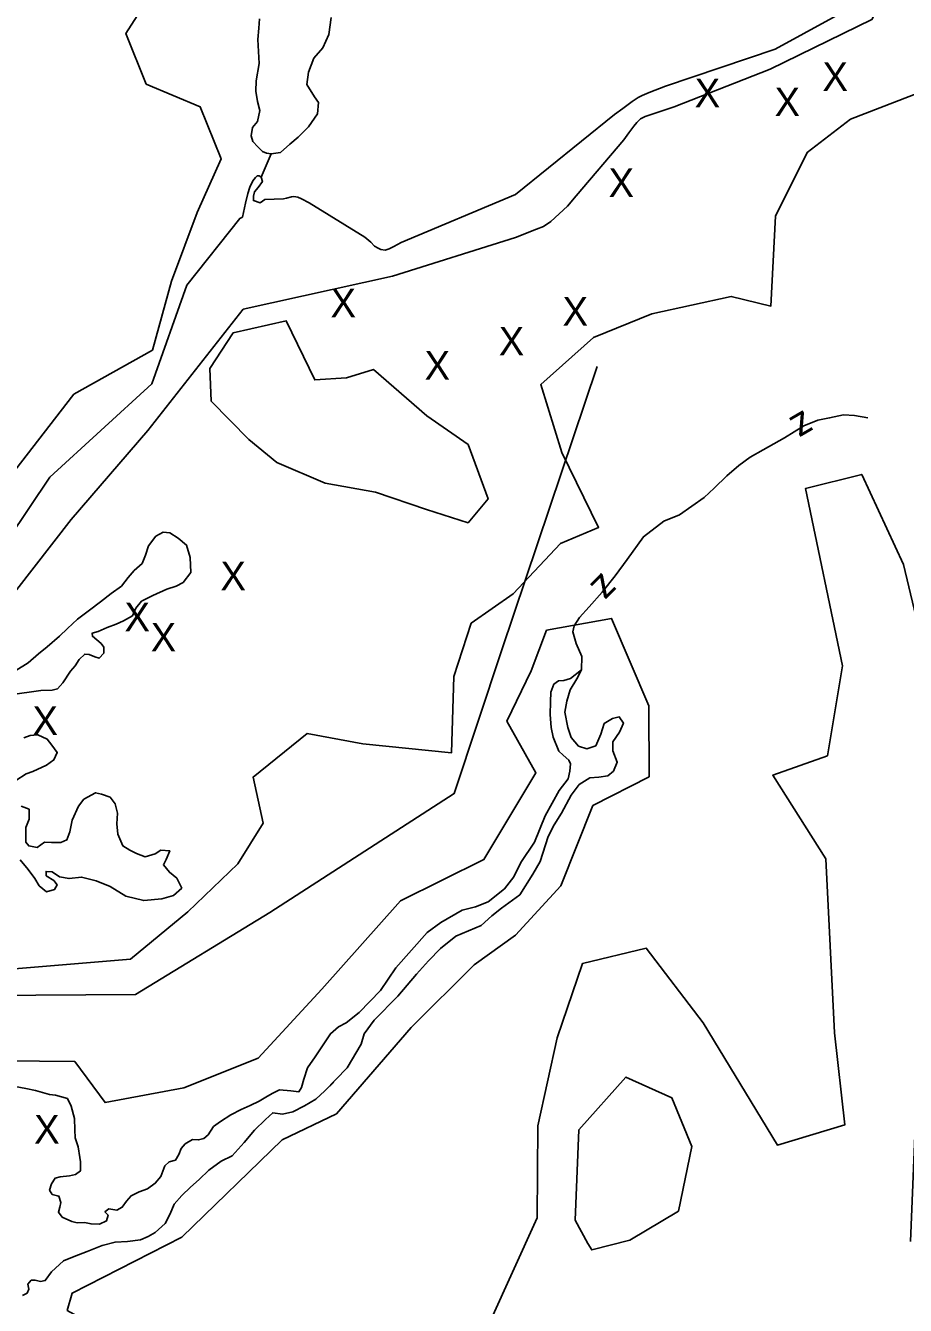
# Model space of a CAD drawing. Extents: x 2030130 to 2036320, y 723205 to 762423.
# Drawn here: x 2033764.6 to 2034072.5, y 737672 to 738120 of the extents above; entities that cross this region are included whole.
import ezdxf

# ---------------------------------------------------------------- set-up
doc = ezdxf.new("R2010")
doc.units = 0
for name, color, linetype in [('Draft_Station Tics Major', 7, 'Continuous'), ('Exist Terrain Model Ground Surface', 7, 'Continuous'), ('Prop Alignment Horizontal', 7, 'Continuous')]:
    doc.layers.add(name, color=color, linetype=linetype)

msp = doc.modelspace()

# ---------------------------------------------------------------- linework, layer by layer
at = {"layer": 'Draft_Station Tics Major'}
for points in [[(2033808.7, 738131.37), (2033799.69, 738117.2), (2033806.81, 738099.51), (2033825.75, 738091.59), (2033833, 738073.37), (2033824.68, 738054.57), (2033815.71, 738030.52), (2033808.99, 738006.41), (2033781.5, 737990.94), (2033760.88, 737964.24)], [(2033821.42, 737809.76), (2033838.93, 737826.64), (2033847.8, 737840.82), (2033844.2, 737856.97), (2033863.12, 737872.24), (2033882.68, 737868.65), (2033913.72, 737865.47), (2033914.43, 737892.21), (2033920.51, 737910.79), (2033935.23, 737921.14), (2033951.83, 737938.71), (2033965.13, 737944.34), (2033952.26, 737970.59), (2033944.88, 737994.34), (2033963.42, 738010.81), (2033983.77, 738019.06), (2034011.58, 738025.18), (2034025.48, 738021.84), (2034027.09, 738053.3), (2034038.12, 738075.6), (2034053.27, 738087.26), (2034084.11, 738099.11)], [(2033842.69, 737975.16), (2033829.56, 737988.48), (2033829.02, 737999.95), (2033837.19, 738012.41), (2033855.84, 738016.6), (2033865.79, 737995.98), (2033876.86, 737996.66), (2033886.41, 737999.61), (2033905.01, 737983.41)], [(2033905.01, 737983.41), (2033919.53, 737973.35), (2033926.49, 737954.37), (2033919.46, 737945.97), (2033904.95, 737950.63), (2033887.05, 737956.68), (2033869.48, 737959.83), (2033852.52, 737967.05), (2033842.69, 737975.16)], [(2034074.32, 737694.44), (2034079.7, 737825.59), (2034079.96, 737897.68), (2034071.87, 737931.33), (2034057.27, 737962.89), (2034037.52, 737957.92), (2034050.53, 737895.95), (2034045.23, 737864.43), (2034026.1, 737857.6), (2034044.7, 737828.33), (2034047.72, 737767.38), (2034051.36, 737735.27), (2034027.75, 737728.14), (2034001.8, 737770.89), (2033981.81, 737797.02), (2033959.55, 737791.71), (2033950.68, 737765.68), (2033943.94, 737734.85), (2033943.63, 737702.7)], [(2033819.33, 737695.93), (2033854.34, 737729.96), (2033873.39, 737739.03), (2033899.49, 737769.3), (2033921.58, 737791.23), (2033936.04, 737801.58), (2033951.97, 737818.9), (2033963.13, 737846.99), (2033982.86, 737857.1), (2033982.74, 737881.88), (2033969.71, 737912.48), (2033946.95, 737908.37), (2033941.5, 737894.12), (2033933.07, 737876.51), (2033943.22, 737858.5), (2033925.02, 737828.05), (2033895.84, 737813.67), (2033868.28, 737782.77), (2033846, 737758.61), (2033819.95, 737748.24), (2033792.42, 737743.05), (2033781.79, 737757.38), (2033744.5, 737757.8)], [(2033726.95, 737787.05), (2033801.29, 737793.2), (2033821.42, 737809.76)], [(2033956.92, 737701.88), (2033958.27, 737733.49), (2033974.63, 737751.97), (2033990.81, 737744.63), (2033997.82, 737727.61), (2033993.11, 737705.05), (2033976.14, 737694.87), (2033962.76, 737691.48), (2033961.38, 737693.74)], [(2033943.63, 737702.7), (2033926.93, 737665.92), (2033904.97, 737641.26), (2033885.57, 737631.2), (2033855.14, 737633.82), (2033829.51, 737649.23), (2033803.66, 737663.3), (2033785.04, 737666.93), (2033779.15, 737670.19), (2033780.87, 737676.32), (2033819.33, 737695.93)], [(2033961.38, 737693.74), (2033956.92, 737701.88)]]:
    msp.add_lwpolyline(points, dxfattribs=at)
at = {"layer": 'Exist Terrain Model Ground Surface'}
msp.add_lwpolyline([(2033964.63, 738000.66), (2033931.26, 737901.48), (2033914.62, 737851.16), (2033850.12, 737809.52), (2033803.03, 737780.8), (2033680.98, 737780.05), (2033616.14, 737770.94)], dxfattribs=at)
at = {"layer": 'Prop Alignment Horizontal'}
for points in [[(2034066, 738152.73), (2034057.08, 738128.21), (2034026.99, 738111.77), (2033988.61, 738098.76)], [(2033991.65, 738091.61), (2034025.22, 738104.79), (2034060.8, 738122.09), (2034070.76, 738140.25)], [(2033846.41, 738122.33), (2033846.27, 738119.11), (2033845.85, 738115.1), (2033846.39, 738106.67), (2033845.28, 738100.64), (2033845.13, 738097.09), (2033845.77, 738093.39), (2033846.63, 738090.27), (2033845.75, 738086.48), (2033844.06, 738084.34), (2033843.54, 738081.46), (2033844.09, 738079.4), (2033845.89, 738077.59), (2033847.5, 738075.97), (2033848.87, 738075.35), (2033850.57, 738075.05), (2033853.81, 738075.57)], [(2033871.49, 738122.77), (2033870.71, 738116.93), (2033868.63, 738112.23), (2033865.52, 738108.62), (2033863.57, 738103.66), (2033863.08, 738099.33), (2033865.75, 738095.05), (2033867.09, 738093.12), (2033866.81, 738089.11), (2033863.61, 738084.57), (2033859.98, 738080.9), (2033857.03, 738078.53), (2033853.81, 738075.57)], [(2033970.77, 738088.92), (2033973.67, 738090.96), (2033976.92, 738093.44), (2033979, 738094.8), (2033980.43, 738095.58), (2033982.84, 738096.63), (2033988.61, 738098.76)], [(2033973.96, 738079.96), (2033975.75, 738082.44), (2033977.5, 738084.85), (2033978.55, 738086.08), (2033979.85, 738087.38), (2033981.41, 738088.23), (2033983.94, 738088.95), (2033991.65, 738091.61)], [(2033970.77, 738088.92), (2033936.03, 738060.82), (2033895.99, 738044.12)], [(2033957.29, 738060.43), (2033973.96, 738079.96)], [(2033850.57, 738075.05), (2033847.09, 738066.9)], [(2033844.13, 738065.62), (2033843.13, 738063.43), (2033842.35, 738061.2), (2033841.55, 738057.86), (2033840.48, 738052.92)], [(2033844.13, 738065.62), (2033845.03, 738066.8), (2033845.62, 738067.39), (2033846.32, 738067.39)], [(2033854.85, 738059.36), (2033848.31, 738059.16), (2033846.64, 738058.01), (2033844.34, 738058.72), (2033844.31, 738060.3), (2033844.68, 738061.81), (2033846.03, 738063.37), (2033847.46, 738065.44), (2033847.09, 738066.9), (2033846.32, 738067.39)], [(2033854.85, 738059.36), (2033855.97, 738059.54), (2033857.65, 738060.1), (2033858.43, 738060.21), (2033859.88, 738059.99), (2033861.21, 738059.32), (2033863.84, 738058.01)], [(2033936.05, 738045.81), (2033943.42, 738048.71), (2033945.86, 738049.72), (2033948.43, 738051.43), (2033954.31, 738056.74), (2033957.29, 738060.43)], [(2033883.32, 738045.89), (2033863.84, 738058.01)], [(2033840.48, 738052.92), (2033839.55, 738052.5), (2033821.06, 738029.09)], [(2033664.33, 737850.64), (2033706.74, 737866.99), (2033748.47, 737905.92), (2033780.57, 737947.09), (2033807.33, 737978.27), (2033840.77, 738020.75), (2033893, 738032.33), (2033936.05, 738045.81)], [(2033883.32, 738045.89), (2033885.41, 738044.14), (2033886.75, 738042.81), (2033887.98, 738042.14), (2033888.98, 738041.58), (2033890.43, 738041.35), (2033891.88, 738041.8), (2033893.44, 738042.69), (2033895.99, 738044.12)], [(2033821.06, 738029.09), (2033808.81, 737994.65), (2033773.1, 737961.98), (2033743.74, 737918.37), (2033703.21, 737889.06), (2033644.85, 737858.08)], [(2034059.38, 737982.66), (2034054.72, 737983.48), (2034050.9, 737983.7), (2034045.99, 737982.69), (2034041.89, 737981.92), (2034036.96, 737979.85), (2034030.21, 737975.71), (2034022.73, 737971.46), (2034018.19, 737968.92), (2034014.24, 737965.97), (2034010.07, 737962.43), (2034005.62, 737958.05), (2034002.05, 737954.76), (2033993.42, 737948.75), (2033988.02, 737946.5), (2033980.85, 737941.05), (2033975.14, 737933.13), (2033970.99, 737927.35), (2033966.45, 737921.71), (2033961.85, 737916.6), (2033958.47, 737912.79), (2033956.56, 737909.93), (2033956.18, 737907.76), (2033957.28, 737903.71), (2033959.29, 737899.18), (2033959.19, 737894.5), (2033957.54, 737891.37)], [(2033761.21, 737894.22), (2033765.49, 737896.9), (2033769.05, 737900.05), (2033772.14, 737902.49), (2033776.44, 737906.29), (2033779.27, 737908.99), (2033782.71, 737912.22), (2033786.93, 737915.35), (2033790.82, 737918.3), (2033794.58, 737921.25), (2033798.19, 737923.81), (2033800.5, 737926.8), (2033802.6, 737929.32), (2033805.36, 737931.77), (2033806.54, 737934.58), (2033807.6, 737937.92), (2033810.12, 737941.23), (2033812.79, 737942.68), (2033815.09, 737942.44), (2033818.01, 737940.53), (2033820.86, 737938.16), (2033822.15, 737933.84), (2033822.37, 737928.56), (2033819.79, 737925.12), (2033817.32, 737923.79), (2033814, 737922.68), (2033809.14, 737920.54), (2033805.2, 737918.58), (2033803.23, 737916.12), (2033801.99, 737913.44), (2033798.85, 737911.6), (2033796.25, 737910.47), (2033793.13, 737909.35), (2033790, 737907.9), (2033787.87, 737907.29), (2033787.98, 737906.23), (2033791.09, 737903.66), (2033791.92, 737902.45), (2033792.01, 737900.34), (2033790.39, 737898.53), (2033788.81, 737899.02), (2033786.85, 737899.92), (2033785.27, 737900.03), (2033783.32, 737898.16), (2033781.89, 737895.88), (2033780.33, 737894.07), (2033777.67, 737889.97), (2033775.71, 737887.9), (2033773.92, 737887.41), (2033769.89, 737887.24), (2033765.86, 737886.73), (2033759.84, 737885.88)], [(2033959.19, 737894.5), (2033955.3, 737891.42), (2033953.04, 737890.81), (2033951.06, 737890.59), (2033949.52, 737889.44), (2033948.47, 737886.69), (2033948.26, 737883.27), (2033948.16, 737878.85), (2033948.59, 737874.29), (2033949.24, 737870.98), (2033951.25, 737866.05), (2033952.8, 737864.64), (2033954.74, 737862.88), (2033955.3, 737861.61), (2033955.11, 737858.98), (2033954.46, 737856.29)], [(2033957.54, 737891.37), (2033955.21, 737887.47), (2033954, 737883.54), (2033953.39, 737879.72), (2033954.33, 737874.3), (2033955.5, 737870.78), (2033958.14, 737867.82), (2033961.09, 737866.89), (2033964.15, 737867.88), (2033965.88, 737871.93), (2033967.09, 737875.67), (2033970.03, 737877.51), (2033972.41, 737877.99), (2033973.82, 737875.85), (2033972.43, 737872.71), (2033970.11, 737869.33), (2033970.11, 737866.17), (2033971.67, 737862.18), (2033970.41, 737859.04), (2033968.33, 737857.44), (2033965.23, 737856.98), (2033962.05, 737856.65), (2033958.38, 737854.36)], [(2033763.99, 737870.68), (2033766.19, 737871.56), (2033768.89, 737871.7), (2033772.16, 737870.24), (2033773.76, 737868.16), (2033775.68, 737865.55), (2033774.5, 737862.94), (2033771.96, 737861.08), (2033767.16, 737858.94), (2033764.77, 737858.07), (2033761.16, 737855.78)], [(2033954.46, 737856.29), (2033951.4, 737852.27), (2033946.4, 737843.34), (2033942.77, 737834.19), (2033937.93, 737827.04), (2033935.44, 737822.08), (2033932.19, 737817.87), (2033926.48, 737813.25), (2033922.09, 737811.5), (2033917.45, 737810.34), (2033909.97, 737806.02), (2033905.14, 737802.57), (2033894.19, 737790.21), (2033888.8, 737782.22), (2033881.38, 737774.53), (2033876.75, 737770.88), (2033874.08, 737769.48), (2033871.33, 737767.1), (2033866, 737758.98)], [(2033958.38, 737854.36), (2033955.52, 737850.66), (2033952.15, 737844.34), (2033949.62, 737840.24), (2033947.49, 737836.2), (2033944.66, 737827.36), (2033942.19, 737822.99), (2033937.61, 737815.77), (2033931.18, 737811.03), (2033927.82, 737808.4), (2033924.06, 737804.99), (2033915.14, 737801.23), (2033909.77, 737796.93), (2033905.65, 737792.66), (2033901.46, 737788.01), (2033894.89, 737780.3), (2033886.6, 737771.85), (2033883.13, 737767.04), (2033882.06, 737763.51), (2033877.13, 737755.17), (2033869.37, 737747.1)], [(2033768.62, 737832.33), (2033771.17, 737834.12), (2033773.67, 737834), (2033776.91, 737834.06), (2033778.97, 737834.94), (2033780.02, 737837.82), (2033780.9, 737841.89), (2033783.05, 737846.79), (2033784.95, 737849.19), (2033789.09, 737851.47), (2033791.19, 737850.96), (2033794.14, 737849.98), (2033795.93, 737847.63), (2033796.72, 737844.31), (2033796.57, 737840.56), (2033796.82, 737836.92), (2033798.64, 737832.86), (2033801.11, 737831.36), (2033803.46, 737830.18), (2033806.47, 737829.06), (2033809.92, 737830.11), (2033811.93, 737831.32), (2033815.03, 737831.18), (2033813.84, 737828.11), (2033812.81, 737826.22), (2033814.93, 737823.67), (2033817.52, 737821.57), (2033819.22, 737818.1), (2033816.33, 737815.53), (2033812.28, 737814.36), (2033805.94, 737813.71), (2033799.64, 737815.3), (2033794.18, 737818.65), (2033789.27, 737820.67), (2033784.16, 737821.97), (2033779.79, 737821.4), (2033776.51, 737822.07), (2033773.91, 737823.78), (2033771.74, 737823.95), (2033771.84, 737822.44), (2033774.5, 737820.73), (2033775.59, 737819.19), (2033774.76, 737817.56), (2033771.91, 737816.83), (2033769.32, 737818.93), (2033767.79, 737821.4), (2033765.49, 737824.62), (2033762.66, 737828.04)], [(2033763.01, 737846.83), (2033765.82, 737845.72), (2033765.87, 737842.22), (2033764.62, 737839.34), (2033764.64, 737834.13), (2033765.67, 737832.86), (2033768.62, 737832.33)], [(2033759.02, 737749.05), (2033764.67, 737748.01), (2033768.01, 737747.21), (2033773, 737745.91), (2033775.1, 737745.6), (2033779.23, 737744.46), (2033780.49, 737741.79), (2033781.65, 737737.48), (2033781.82, 737733.45), (2033781.96, 737730.68), (2033782.95, 737727.56), (2033783.53, 737723.85), (2033783.76, 737722.33), (2033783.75, 737719.1), (2033782.01, 737717.82), (2033779.96, 737717.4), (2033776.65, 737717.01), (2033774.93, 737716.52), (2033773.7, 737714.57), (2033772.99, 737712.41), (2033773.94, 737710.87), (2033775.71, 737710.37), (2033776.24, 737710.3), (2033776.98, 737708.04), (2033776.62, 737706.4), (2033776.05, 737704.69), (2033777.4, 737702.88), (2033780.79, 737701.36), (2033782.69, 737700.92), (2033785.2, 737701), (2033787.5, 737700.55), (2033790.4, 737700.42), (2033792.93, 737701.62), (2033793.44, 737703.59), (2033792.34, 737704.73), (2033793.75, 737705.82), (2033796.51, 737705.37), (2033798.44, 737706.38), (2033799.87, 737708.46), (2033801.5, 737710.4), (2033804.37, 737711.79), (2033807.22, 737712.85), (2033809.97, 737714.77), (2033811.93, 737717.1), (2033813.34, 737720.89), (2033814.88, 737722.24), (2033817.01, 737722.92), (2033818.24, 737724.87), (2033819.01, 737726.9), (2033820.43, 737728.58), (2033823.03, 737730.11), (2033825.14, 737729.93), (2033826.93, 737730.42), (2033828.48, 737731.7), (2033830.39, 737734.63), (2033832.8, 737736.36), (2033836.48, 737738.72), (2033840.01, 737740.55), (2033843.21, 737742), (2033846.34, 737743.51), (2033848.68, 737744.91), (2033850.89, 737746.25), (2033853.49, 737747.51), (2033857.44, 737747.1), (2033860.27, 737746.84), (2033861.22, 737748.33), (2033862.01, 737751.22), (2033863.22, 737755.21), (2033866, 737758.98)], [(2033872.47, 737750.13), (2033869.37, 737747.1), (2033866.14, 737744.27), (2033862.2, 737741.91), (2033858.13, 737739.83), (2033854.55, 737738.98), (2033851.07, 737739.45), (2033848.51, 737737.14), (2033844.74, 737733.39), (2033841.08, 737729.06), (2033836.89, 737724.4), (2033833.09, 737722.57), (2033828.67, 737719.37), (2033825.37, 737716.14), (2033822.27, 737713.38), (2033819.24, 737710.47), (2033816.6, 737707.5), (2033815.14, 737704.1)], [(2033815.14, 737704.1), (2033813.47, 737700.74), (2033809.97, 737697.5), (2033807.44, 737696.19), (2033804.85, 737694.96), (2033800.31, 737694.43), (2033795.91, 737694.17), (2033791.35, 737692.99), (2033786.11, 737690.85), (2033781.6, 737689.14), (2033777.83, 737687.68), (2033773.65, 737683.8), (2033771.46, 737680.71), (2033769.81, 737680.43), (2033767.99, 737680.81), (2033766.55, 737680.86), (2033765.39, 737679.45), (2033765.67, 737677.67), (2033765.17, 737676.37), (2033763.51, 737675.44)]]:
    msp.add_lwpolyline(points, dxfattribs=at)

# ---------------------------------------------------------------- texts
at = {"layer": 'Draft_Station Tics Major'}
for p in [(2034043.5, 738097.15), (2033998.79, 738091.42), (2034026.74, 738088.31), (2033968.64, 738059.99), (2033871.32, 738017.93), (2033952.53, 738014.97), (2033930.21, 738004.54), (2033904.24, 737996.04), (2033832.79, 737922.37), (2033799.2, 737907.98), (2033808.39, 737900.94), (2033766.98, 737871.73), (2033767.58, 737728.7)]:
    msp.add_text('X', height=10, dxfattribs=at).set_placement(p)
at = {"layer": 'Prop Alignment Horizontal'}
for rotation, p in [(210.1087, (2034037.04, 737985.62)), (225.545, (2033966.37, 737928.78))]:
    msp.add_text('z', height=10, rotation=rotation, dxfattribs=at).set_placement(p)

doc.saveas('drawing.dxf')
